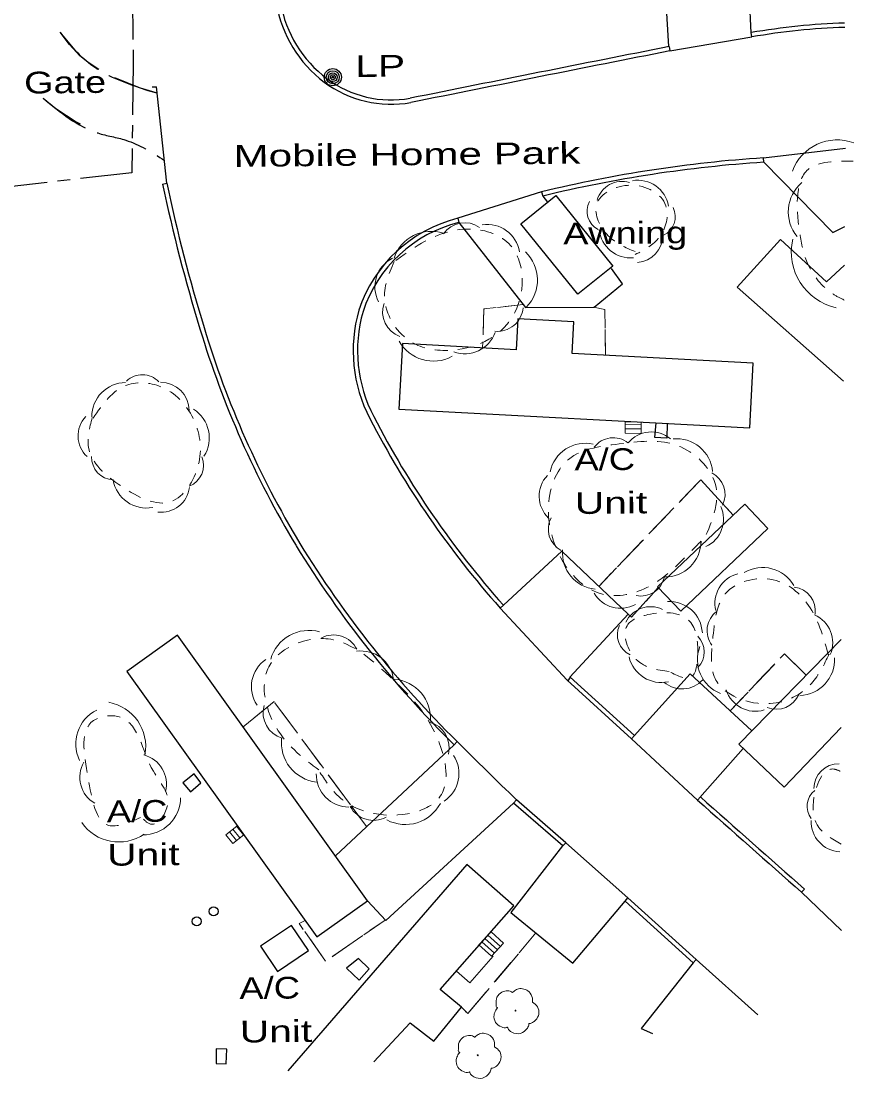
# Model space of a CAD drawing. Extents: x 2362213 to 2366494, y 6968794 to 6978110.
# Drawn here: x 2364841.6 to 2365025.4, y 6968869.7 to 6969103.1 of the extents above; entities that cross this region are included whole.
import ezdxf

# ---------------------------------------------------------------- set-up
doc = ezdxf.new("R2010")
doc.units = 0
doc.header["$LTSCALE"] = 1.9
for name, pattern in [('LONG_DASH_SHORT_DASH', [9.9, 6, -1.2, 1.5, -1.2]), ('LONG_DASHED', [7.5, 6, -1.5]), ('MEDIUM_DASHED', [4.5, 3, -1.5]), ('SHORT_DASHED', [2.7, 1.5, -1.2])]:
    doc.linetypes.add(name, pattern=pattern)
for name, color, linetype, lineweight in [('11', 7, 'Continuous', 25), ('14', 7, 'Continuous', 13), ('15', 7, 'Continuous', 13), ('16', 7, 'Continuous', 13), ('17', 7, 'Continuous', 25), ('2', 7, 'Continuous', 25), ('20', 7, 'Continuous', 25), ('21', 7, 'Continuous', 25), ('23', 7, 'Continuous', 25), ('29', 7, 'Continuous', 13), ('3', 7, 'Continuous', 25)]:
    doc.layers.add(name, color=color, linetype=linetype, lineweight=lineweight)

msp = doc.modelspace()

# ---------------------------------------------------------------- linework, layer by layer
at = {"layer": '11'}
for points in [[(2364972.172, 6969049.046), (2364964.472, 6969042.813), (2364951.893, 6969058.355), (2364959.604, 6969064.587)], [(2365003.187, 6969027.631), (2364963.247, 6969029.731), (2364963.62, 6969036.755), (2364951.222, 6969037.417), (2364950.857, 6969030.584), (2364925.763, 6969031.925), (2364924.99, 6969017.506), (2365002.423, 6969013.364)], [(2365001.314, 6968996.521), (2364982.087, 6968978.248), (2364987.169, 6968972.896), (2365006.406, 6968991.161)], [(2364918.054, 6968908.985), (2364876.134, 6968967.578), (2364864.979, 6968959.602), (2364906.889, 6968900.998)], [(2364901.304, 6968903.545), (2364894.468, 6968898.94), (2364898.212, 6968893.375), (2364905.048, 6968897.98)]]:
    msp.add_lwpolyline(points, close=True, dxfattribs=at)
for points in [[(2365023.313, 6969049.213), (2365019.347, 6969045.605), (2365009.179, 6969054.92), (2364999.618, 6969044.377), (2365023.086, 6969023.63)], [(2365022.579, 6968966.604), (2364999.968, 6968943.537), (2365010, 6968934.071), (2365022.554, 6968947.221)]]:
    msp.add_lwpolyline(points, dxfattribs=at)
at = {"layer": '14'}
for p, q in [((2364952.442, 6969040.558), (2364948.466, 6969040.12)), ((2364943.521, 6969032.354), (2364943.474, 6969030.973)), ((2364970.58, 6969029.341), (2364970.522, 6969033.341)), ((2364993.916, 6968999.391), (2364998.776, 6968994.107)), ((2364980.145, 6968989.931), (2364985.672, 6968995.712)), ((2364973.234, 6968982.703), (2364978.759, 6968988.487)), ((2364969.085, 6968978.364), (2364971.848, 6968981.26)), ((2364979.526, 6968975.133), (2364982.208, 6968978.119)), ((2365002.246, 6968955.268), (2365007.773, 6968961.051)), ((2364902.408, 6968946.247), (2364897.647, 6968952.672)), ((2364998.108, 6968950.929), (2365000.87, 6968953.825)), ((2364896.155, 6968951.878), (2364890.597, 6968947.365)), ((2364908.355, 6968938.214), (2364903.593, 6968944.639)), ((2364914.301, 6968930.17), (2364909.54, 6968936.605)), ((2364917.869, 6968925.344), (2364915.487, 6968928.561)), ((2364921.965, 6968904.732), (2364918.677, 6968902.46)), ((2364908.79, 6968895.667), (2364904.207, 6968902.222)), ((2364917.027, 6968901.325), (2364910.439, 6968896.783)), ((2364955.223, 6968901.888), (2364952.642, 6968898.834)), ((2364951.356, 6968897.302), (2364946.204, 6968891.182))]:
    msp.add_line(p, q, dxfattribs=at)
at = {"layer": '14', "linetype": 'MEDIUM_DASHED'}
for points in [[(2364952.442, 6969040.558), (2364943.752, 6969039.605), (2364943.474, 6969030.973)], [(2364970.58, 6969029.341), (2364970.443, 6969039.449), (2364967.898, 6969039.975)], [(2364969.085, 6968978.364), (2364991.592, 6969001.909), (2364998.776, 6968994.107)], [(2364975.402, 6968972.374), (2364976.32, 6968971.582), (2364982.208, 6968978.119)], [(2364998.108, 6968950.929), (2365010.05, 6968963.444), (2365014.894, 6968958.769)], [(2364917.869, 6968925.344), (2364897.455, 6968952.93), (2364890.597, 6968947.365)], [(2364921.965, 6968904.732), (2364908.8, 6968895.657), (2364902.98, 6968903.991), (2364904.294, 6968904.623)], [(2364955.223, 6968901.888), (2364940.213, 6968884.075), (2364938.737, 6968885.561)]]:
    msp.add_lwpolyline(points, dxfattribs=at)
at = {"layer": '14'}
for points in [[(2364946.478, 6969039.901), (2364943.752, 6969039.605), (2364943.582, 6969034.354)], [(2364970.493, 6969035.341), (2364970.443, 6969039.449), (2364967.898, 6969039.975)], [(2364987.058, 6968997.156), (2364991.592, 6969001.909), (2364992.562, 6969000.858)], [(2364975.402, 6968972.374), (2364976.32, 6968971.582), (2364978.19, 6968973.65)], [(2365009.149, 6968962.505), (2365010.05, 6968963.444), (2365014.874, 6968958.789)], [(2364903.071, 6968903.862), (2364902.98, 6968903.991), (2364904.294, 6968904.623)], [(2364944.92, 6968889.65), (2364940.213, 6968884.075), (2364939.718, 6968884.57)]]:
    msp.add_lwpolyline(points, dxfattribs=at)
at = {"layer": '15'}
msp.add_lwpolyline([(2364945.791, 6968896.729), (2364940.658, 6968890.859), (2364937.672, 6968893.481)], dxfattribs=at)
at = {"layer": '16'}
for p, q in [((2364974.913, 6969012.162), (2364974.95, 6969014.671)), ((2364974.924, 6969013.162), (2364978.445, 6969013.115)), ((2364974.944, 6969014.162), (2364978.465, 6969014.116)), ((2364974.95, 6969014.671), (2364978.47, 6969014.625)), ((2364978.434, 6969012.115), (2364978.47, 6969014.625)), ((2364974.913, 6969012.162), (2364978.434, 6969012.115)), ((2364886.813, 6968923.548), (2364889.215, 6968925.471)), ((2364889.126, 6968922.27), (2364887.597, 6968924.175)), ((2364889.9, 6968922.897), (2364888.371, 6968924.803)), ((2364890.684, 6968923.515), (2364889.156, 6968925.42)), ((2364890.743, 6968923.565), (2364889.215, 6968925.471)), ((2364888.341, 6968921.642), (2364886.813, 6968923.548)), ((2364888.341, 6968921.642), (2364890.743, 6968923.565)), ((2364945.321, 6968902.164), (2364942.668, 6968899.249)), ((2364947.421, 6968898.904), (2364944.648, 6968901.428)), ((2364948.094, 6968899.64), (2364945.321, 6968902.164)), ((2364945.442, 6968896.726), (2364942.668, 6968899.249)), ((2364946.075, 6968897.422), (2364943.302, 6968899.945)), ((2364946.748, 6968898.157), (2364943.975, 6968900.681)), ((2364948.094, 6968899.64), (2364945.442, 6968896.726))]:
    msp.add_line(p, q, dxfattribs=at)
at = {"layer": '17', "linetype": 'LONG_DASH_SHORT_DASH'}
msp.add_lwpolyline([(2364796.542, 6969225.692), (2364797.507, 6969269.253), (2364797.233, 6969290.752), (2364795.774, 6969303.179), (2364823.196, 6969305.26), (2364864.02, 6969308.159), (2364864.708, 6969225.341), (2364865.984, 6969129.23), (2364866.361, 6969093.811), (2364866.081, 6969069.657), (2364832.486, 6969065.827), (2364808.015, 6969063.684), (2364796.469, 6969063.264), (2364796.133, 6969123.774), (2364795.899, 6969184.005), (2364795.966, 6969216.847)], dxfattribs=at)
at = {"layer": '2'}
for p, q in [((2365002.734, 6969100.491), (2365001.988, 6969114.723)), ((2364984.811, 6969096.54), (2365002.882, 6969099.622)), ((2365002.882, 6969099.622), (2365002.723, 6969100.571)), ((2364984.622, 6969097.478), (2364984.811, 6969096.54)), ((2364870.571, 6969088.591), (2364871.531, 6969088.61)), ((2364873.794, 6969067.34), (2364871.531, 6969088.61)), ((2365005.477, 6969072.926), (2365023.537, 6969075.058)), ((2365005.536, 6969071.966), (2365005.477, 6969072.926)), ((2364872.856, 6969067.141), (2364873.794, 6969067.34)), ((2364956.496, 6969065.418), (2364938, 6969059.592)), ((2364956.496, 6969065.418), (2364956.724, 6969064.49)), ((2364956.724, 6969064.49), (2364957.797, 6969063.13)), ((2364962.766, 6968958.343), (2364976.959, 6968945.457)), ((2364976.959, 6968945.457), (2364976.315, 6968944.752)), ((2364937.186, 6968943.429), (2364910.969, 6968918.889)), ((2364937.186, 6968943.429), (2364937.86, 6968944.116)), ((2364976.315, 6968944.752), (2364990.886, 6968931.179)), ((2364991.421, 6968931.784), (2365000.977, 6968942.587)), ((2364950.31, 6968930.503), (2364950.943, 6968931.229)), ((2364991.52, 6968931.895), (2364990.886, 6968931.179)), ((2364961.17, 6968921.077), (2364950.31, 6968930.503)), ((2364961.17, 6968921.077), (2364961.804, 6968921.802)), ((2365013.861, 6968910.857), (2365014.494, 6968911.573)), ((2365013.861, 6968910.857), (2365022.651, 6968902.41)), ((2364974.897, 6968908.896), (2364975.54, 6968909.612)), ((2364989.928, 6968895.319), (2364974.897, 6968908.896))]:
    msp.add_line(p, q, dxfattribs=at)
for points in [[(2364984.533, 6969097.467), (2364983.283, 6969118.366), (2365001.479, 6969119.83)], [(2365005.536, 6969071.966), (2365020.734, 6969056.42), (2365023.381, 6969057.805)], [(2364938, 6969059.592), (2364938.229, 6969058.665), (2364952.938, 6969039.923), (2364968.078, 6969039.977), (2364974.36, 6969045.107), (2364971.897, 6969048.534)], [(2364962.737, 6968958.292), (2364975.564, 6968972.215), (2364960.921, 6968986.107), (2364948.054, 6968974.223)], [(2364948.054, 6968974.223), (2364947.34, 6968973.586), (2364962.123, 6968957.636), (2364976.315, 6968944.752)], [(2364962.766, 6968958.343), (2364962.254, 6968957.518), (2364962.442, 6968957.73)], [(2364976.919, 6968945.417), (2364989.261, 6968959.085), (2365002.89, 6968946.514)], [(2364975.54, 6968909.612), (2364961.804, 6968921.802), (2364950.943, 6968931.229)], [(2364918.054, 6968908.985), (2364922.086, 6968904.593), (2364950.31, 6968930.503)], [(2364961.12, 6968921.126), (2364949.71, 6968906.386), (2364963.387, 6968895.247), (2364974.897, 6968908.896)], [(2365004.207, 6968883.844), (2364990.571, 6968896.036), (2364975.54, 6968909.612)], [(2364990.571, 6968896.036), (2364989.928, 6968895.319), (2364978.484, 6968880.829), (2364980.925, 6968879.662)]]:
    msp.add_lwpolyline(points, dxfattribs=at)
for centre, radius, start, end in [((2364925.223, 6969111.749), 27.705, 189.86516, 232.93176), ((2364925.223, 6969111.749), 26.745, 189.86516, 232.93176), ((2365028.157, 6968953.666), 149.088, 91.84691, 99.82445), ((2365028.157, 6968953.666), 148.128, 91.84691, 99.82445), ((2368305.562, 6952303.171), 17119.506, 101.18547, 101.38057), ((2368305.562, 6952303.171), 17118.546, 101.18547, 101.38057), ((2364923.316, 6969109.582), 23.868, 233.42745, 280.04515), ((2364923.316, 6969109.582), 24.828, 233.42745, 280.04515), ((2365024.197, 6968787.224), 286.314, 93.74901, 103.67769), ((2365024.197, 6968787.224), 285.354, 93.74901, 103.67769), ((2365224.293, 6969140.811), 359.077, 191.83867, 197.10544), ((2365224.293, 6969140.811), 358.117, 191.83867, 197.10544), ((2364945.482, 6969029.642), 30.87, 104.0259, 161.76272), ((2364945.482, 6969029.642), 29.91, 104.0259, 161.76272), ((2364947.108, 6969030.368), 32.209, 163.89503, 207.70198), ((2364947.108, 6969030.368), 31.249, 163.89503, 207.70198), ((2365082.605, 6969095.901), 210.451, 196.76402, 211.05074), ((2365082.605, 6969095.901), 209.491, 196.76402, 211.05074), ((2365098.233, 6969108.138), 202.17, 207.3056, 221.72329), ((2365098.233, 6969108.138), 201.21, 207.3056, 221.72329), ((2365098.694, 6969107.492), 230.219, 211.45841, 225.44935), ((2365098.694, 6969107.492), 229.259, 211.45841, 225.44935), ((2368157.723, 6972200.254), 4579.297, 225.32042, 225.55071), ((2373184.243, 6978170.777), 12349.14, 228.43449, 228.5768), ((2373184.243, 6978170.777), 12348.18, 228.43449, 228.5768)]:
    msp.add_arc(centre, radius, start, end, dxfattribs=at)
at = {"layer": '20'}
for radius in [1.9, 1.442, 0.973, 0.539, 0.192]:
    msp.add_circle((2364910.403, 6969090.721), radius, dxfattribs=at)
at = {"layer": '23'}
for points in [[(2364984.174, 6969014.34), (2364984.135, 6969011.09), (2364981.453, 6969011.234), (2364981.792, 6969014.467)], [(2364919.493, 6968873.408), (2364927.47, 6968882.063), (2364932.679, 6968878.012), (2364938.798, 6968885.511), (2364934.071, 6968889.386), (2364950.345, 6968907.882), (2364939.999, 6968916.964), (2364900.45, 6968871.465)]]:
    msp.add_lwpolyline(points, dxfattribs=at)
for points in [[(2364879.795, 6968937.012), (2364877.323, 6968935.038), (2364879.023, 6968933.014), (2364881.254, 6968934.985)], [(2364918.427, 6968893.958), (2364916.074, 6968896.256), (2364913.415, 6968894.11), (2364916.23, 6968891.456)], [(2364887.054, 6968876.238), (2364884.693, 6968876.345), (2364884.644, 6968873.076), (2364886.905, 6968872.967)]]:
    msp.add_lwpolyline(points, close=True, dxfattribs=at)
for centre in [(2364884.094, 6968906.651), (2364880.395, 6968904.436)]:
    msp.add_circle(centre, 1, dxfattribs=at)
at = {"layer": '29'}
for centre in [(2364950.726, 6968884.745), (2364942.379, 6968874.885)]:
    msp.add_circle(centre, 0.1, dxfattribs=at)
for centre, radius, start, end in [((2365021.732, 6969066.322), 10.567, 69.78723, 159.78723), ((2364974.235, 6969061.982), 5.742, 73.4627, 163.4627), ((2364977.727, 6969061.104), 6.887, 9.99633, 99.99633), ((2365019.356, 6969060.984), 8.444, 129.93906, 219.93906), ((2364971.108, 6969061.149), 4.589, 151.95875, 241.95875), ((2364981.385, 6969059.962), 4.589, 296.11363, 26.11363), ((2364939.537, 6969052.871), 5.729, 55.36233, 145.36233), ((2364944.503, 6969051.067), 7.168, 8.92447, 98.92447), ((2364932.099, 6969048.117), 8.598, 71.65189, 161.65189), ((2364976.068, 6969057.741), 6.887, 185.73888, 275.73888), ((2364977.398, 6969055.587), 5.742, 272.70669, 2.70669), ((2365024.258, 6969052.213), 12.674, 167.38955, 257.38955), ((2364926.87, 6969044.421), 7.168, 116.98505, 206.98505), ((2364946.966, 6969045.974), 8.598, 316.31795, 46.31795), ((2364927.124, 6969038.915), 5.729, 160.68378, 250.68378), ((2364946.702, 6969040.359), 5.729, 264.68544, 354.68544), ((2364939.515, 6969036.835), 7.168, 250.24147, 340.24147), ((2364932.578, 6969036.669), 8.598, 208.92386, 298.92386), ((2364868.379, 6969020.057), 5.011, 43.96796, 133.96796), ((2364864.758, 6969015.833), 7.521, 90.65193, 180.65193), ((2364872.42, 6969017.153), 6.271, 0.11891, 90.11891), ((2364860.467, 6969011.562), 6.271, 136.75487, 226.75487), ((2364875.637, 6969011.115), 7.521, 327.5694, 57.5694), ((2364972.295, 6969005.839), 5.319, 52.37924, 142.37924), ((2364980.705, 6969005.786), 6.656, 50.4787, 140.4787), ((2364986.264, 6969002.967), 7.983, 5.44025, 95.44025), ((2364966.146, 6969001.959), 7.983, 77.60011, 167.60011), ((2364862.178, 6969006.865), 5.011, 177.98902, 267.98902), ((2364876.881, 6969005.111), 5.011, 291.76994, 21.76994), ((2364869.315, 6969003.178), 7.521, 190.29559, 280.29559), ((2364962.598, 6968998.28), 6.656, 136.69817, 226.69817), ((2364991.655, 6968998.645), 5.319, 333.67521, 63.67521), ((2364872.566, 6969000.996), 6.271, 262.80689, 352.80689), ((2364989.968, 6968993.191), 6.656, 294.76095, 24.76095), ((2364963.273, 6968991.005), 5.319, 152.06181, 242.06181), ((2364983.687, 6968988.415), 7.983, 269.25908, 359.25908), ((2364969.068, 6968985.696), 7.983, 174.6935, 264.6935), ((2365005.257, 6968974.517), 8.01, 30.29015, 120.29015), ((2364978.363, 6968981.547), 5.319, 258.68314, 348.68314), ((2365001.411, 6968974.64), 6.678, 104.04571, 194.04571), ((2365011.554, 6968972.912), 5.337, 352.5514, 82.5514), ((2364973.86, 6968980.175), 6.656, 209.79809, 299.79809), ((2364980.519, 6968967.806), 6.08, 64.15404, 154.15404), ((2364984.669, 6968967.728), 7.293, 3.05187, 93.05187), ((2364998.332, 6968968.571), 5.337, 126.63381, 216.63381), ((2365014.054, 6968965.935), 6.678, 336.74549, 66.74549), ((2364905.122, 6968959.916), 8.734, 74.33939, 164.33939), ((2364978.061, 6968967.669), 4.859, 154.90491, 244.90491), ((2364910.527, 6968961.83), 5.819, 27.03095, 117.03095), ((2364987.531, 6968963.886), 4.859, 315.44331, 45.44331), ((2364916.616, 6968956.834), 7.282, 7.85841, 97.85841), ((2364998.871, 6968962.189), 8.01, 158.75534, 248.75534), ((2364899.723, 6968956.228), 7.282, 124.13213, 214.13213), ((2364982.895, 6968964.438), 7.293, 192.82876, 282.82876), ((2365013.126, 6968962.247), 8.01, 272.55781, 2.55781), ((2364923.241, 6968949.193), 8.734, 355.50288, 85.50288), ((2364987.513, 6968961.801), 6.08, 228.43067, 318.43067), ((2365003.616, 6968957.477), 6.678, 197.08029, 287.08029), ((2365008.308, 6968956.568), 5.337, 247.65978, 337.65978), ((2364859.185, 6968942.996), 9.941, 349.74408, 79.74408), ((2364861.976, 6968943.627), 8.288, 116.22763, 206.22762), ((2364900.833, 6968950.486), 5.819, 164.30134, 254.30134), ((2364930.273, 6968942.762), 5.819, 345.80544, 75.80544), ((2364907.795, 6968943.856), 8.734, 173.34721, 263.34721), ((2364867.074, 6968934.73), 6.623, 345.93749, 75.93749), ((2364930.96, 6968937.067), 7.282, 303.29781, 33.29781), ((2364861.213, 6968936.225), 6.623, 149.68186, 239.68186), ((2365022.083, 6968933.729), 5.51, 89.61648, 179.61648), ((2364914.046, 6968936.933), 7.282, 179.27828, 269.27828), ((2364868.545, 6968931.809), 8.288, 269.36103, 359.36103), ((2365019.47, 6968929.834), 4.403, 127.84911, 217.84911), ((2364919.385, 6968932.541), 5.819, 208.54696, 298.54696), ((2364926.412, 6968934.546), 8.734, 242.29569, 332.29569), ((2365022.589, 6968926.405), 6.609, 177.24221, 267.24221), ((2364863.187, 6968931.911), 9.941, 214.49241, 304.49241)]:
    msp.add_arc(centre, radius, start, end, dxfattribs=at)
at = {"layer": '29', "linetype": 'SHORT_DASHED'}
for points in [[(2365023.246, 6969041.552), (2365020.733, 6969042.918), (2365015.25, 6969049.477), (2365013.531, 6969055.811), (2365015.321, 6969070.388), (2365025.204, 6969072.203)], [(2364977.122, 6969052.235), (2364971.188, 6969055.738), (2364968.603, 6969062.563), (2364976.092, 6969066.884), (2364983.907, 6969062.339), (2364982.492, 6969055.456), (2364977.158, 6969051.615)], [(2364924.299, 6969050.242), (2364928.55, 6969053.222), (2364940.884, 6969057.22), (2364949.638, 6969053.573), (2364950.077, 6969037.915), (2364935.828, 6969030.44), (2364927.236, 6969032.629), (2364921.837, 6969042.037), (2364924.166, 6969050.56)], [(2364857.526, 6969015.513), (2364864.957, 6969022.794), (2364873.034, 6969022.181), (2364879.863, 6969014.886), (2364880.736, 6969005.144), (2364874.733, 6968997.086), (2364863.88, 6969000.393), (2364856.497, 6969009.074), (2364857.315, 6969015.611)], [(2364991.651, 6968988.34), (2364987.353, 6968984.009), (2364980.902, 6968978.736), (2364970.563, 6968976.508), (2364957.992, 6968995.439), (2364962.409, 6969006.352), (2364974.455, 6969009.897), (2364986.501, 6969009.442), (2364994.79, 6969001.07), (2364991.858, 6968987.642)], [(2365019.93, 6968963.408), (2365016.051, 6968956.95), (2365006.924, 6968952.493), (2364994.76, 6968958.027), (2364994.229, 6968966.514), (2364997.457, 6968977.194), (2365008.255, 6968979.657), (2365015.722, 6968973.658), (2365019.792, 6968963.167)], [(2364984.636, 6968959.551), (2364977.369, 6968962.253), (2364975.348, 6968969.673), (2364979.905, 6968972.126), (2364988.847, 6968970.992), (2364990.955, 6968963.882), (2364989.329, 6968958.246), (2364984.324, 6968959.758)], [(2364907.328, 6968937.864), (2364898.376, 6968946.489), (2364896.292, 6968960.59), (2364908.352, 6968966.846), (2364922.973, 6968958.454), (2364931.994, 6968947.879), (2364934.134, 6968932.079), (2364919.511, 6968928.229), (2364911.31, 6968932.391), (2364907.431, 6968937.555)], [(2364867.976, 6968927.339), (2364860.902, 6968925.621), (2364856.412, 6968936.139), (2364857.91, 6968948.944), (2364863.274, 6968949.585), (2364870.819, 6968937.556), (2364873.894, 6968929.865), (2364870.3, 6968925.871), (2364868.114, 6968927.58)], [(2365022.609, 6968921.482), (2365017.451, 6968925.492), (2365016.498, 6968931.063), (2365020.931, 6968938.046), (2365022.396, 6968937.55)]]:
    msp.add_spline(points, degree=3, dxfattribs=at)
at = {"layer": '29'}
for points in [[(2364946.76, 6968885.317), (2364946.78, 6968885.327), (2364946.699, 6968885.396), (2364946.463, 6968886.024), (2364946.501, 6968887.305), (2364947.389, 6968888.603), (2364948.694, 6968889.086), (2364949.816, 6968888.896), (2364950.047, 6968888.768), (2364950.117, 6968888.769), (2364950.167, 6968888.81), (2364950.514, 6968889.103), (2364951.38, 6968889.551), (2364952.591, 6968889.483), (2364953.706, 6968888.893), (2364954.44, 6968887.47), (2364954.448, 6968886.61)], [(2364954.438, 6968886.63), (2364955.578, 6968885.571), (2364955.863, 6968883.984), (2364955.156, 6968882.657), (2364954.501, 6968882.11), (2364953.833, 6968881.894), (2364953.683, 6968881.883), (2364953.664, 6968881.772), (2364953.343, 6968880.869), (2364951.804, 6968879.705), (2364949.911, 6968879.987), (2364949.012, 6968880.928), (2364948.941, 6968881.057), (2364948.821, 6968881.036), (2364947.61, 6968881.155), (2364946.34, 6968882.153), (2364945.995, 6968883.79), (2364946.365, 6968884.813), (2364946.691, 6968885.256), (2364946.76, 6968885.307)], [(2364938.414, 6968875.457), (2364938.433, 6968875.467), (2364938.353, 6968875.536), (2364938.117, 6968876.164), (2364938.155, 6968877.445), (2364939.042, 6968878.743), (2364940.349, 6968879.226), (2364941.471, 6968879.036), (2364941.702, 6968878.908), (2364941.772, 6968878.909), (2364941.821, 6968878.95), (2364942.169, 6968879.243), (2364943.034, 6968879.691), (2364944.245, 6968879.623), (2364945.361, 6968879.033), (2364946.093, 6968877.61), (2364946.102, 6968876.75)], [(2364946.091, 6968876.77), (2364947.232, 6968875.711), (2364947.517, 6968874.125), (2364946.809, 6968872.797), (2364946.154, 6968872.251), (2364945.487, 6968872.034), (2364945.338, 6968872.023), (2364945.319, 6968871.913), (2364944.997, 6968871.009), (2364943.458, 6968869.845), (2364941.565, 6968870.127), (2364940.666, 6968871.068), (2364940.595, 6968871.198), (2364940.475, 6968871.176), (2364939.264, 6968871.295), (2364937.994, 6968872.293), (2364937.648, 6968873.931), (2364938.018, 6968874.953), (2364938.344, 6968875.396), (2364938.414, 6968875.447)]]:
    msp.add_spline(points, degree=3, dxfattribs=at)
at = {"layer": '3'}
for points in [[(2364858.754, 6969092.448), (2364856.409, 6969093.946), (2364854.615, 6969095.41), (2364852.291, 6969097.908), (2364850.265, 6969100.679)], [(2364871.684, 6969087.181), (2364869.689, 6969087.742), (2364867.733, 6969088.414), (2364862.311, 6969090.622)], [(2364846.463, 6969086.111), (2364849.265, 6969083.818), (2364853.744, 6969080.851), (2364854.638, 6969080.4)]]:
    msp.add_lwpolyline(points, dxfattribs=at)
at = {"layer": '3', "linetype": 'LONG_DASHED'}
for points in [[(2364871.684, 6969087.181), (2364867.733, 6969088.414), (2364856.409, 6969093.946), (2364850.265, 6969100.679)], [(2364846.463, 6969086.111), (2364858.557, 6969078.417), (2364864.703, 6969076.835), (2364873.256, 6969072.376)]]:
    msp.add_spline(points, degree=3, dxfattribs=at)

# ---------------------------------------------------------------- texts
at = {"layer": '11'}
for s, width, p in [('Mobile Home Park', 1.45, (2364888.52, 6969070.931)), ('Awning', 1.3, (2364961.257, 6969053.824))]:
    msp.add_text(s, height=4.8, rotation=0.546, dxfattribs=dict(at, width=width)).set_placement(p)
at = {"layer": '20', "width": 1.4}
msp.add_text('  LP', height=4.8, rotation=0.546, dxfattribs=at).set_placement((2364910.402, 6969090.72))
at = {"layer": '21', "width": 1.3}
msp.add_text('Gate', height=4.8, rotation=0.546, dxfattribs=at).set_placement((2364842.314, 6969087.111))
at = {"layer": '23'}
for s, width, p in [('A/C', 1.25, (2364963.742, 6969003.934)), ('Unit', 1.4, (2364963.834, 6968994.334)), ('A/C', 1.25, (2364860.556, 6968926.308)), ('Unit', 1.4, (2364860.647, 6968916.708)), ('A/C', 1.25, (2364889.809, 6968887.295)), ('Unit', 1.4, (2364889.9, 6968877.695))]:
    msp.add_text(s, height=4.8, rotation=0.546, dxfattribs=dict(at, width=width)).set_placement(p)

doc.saveas('drawing.dxf')
